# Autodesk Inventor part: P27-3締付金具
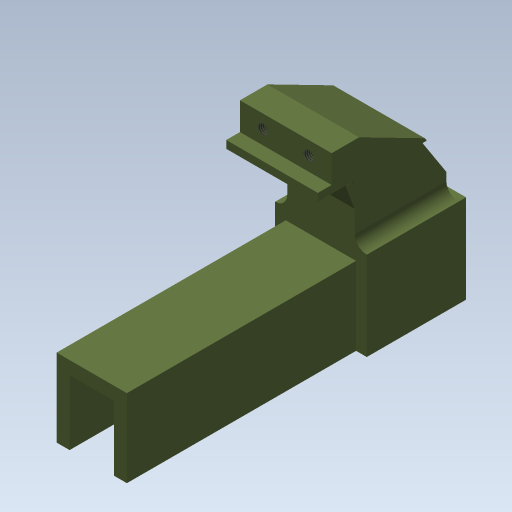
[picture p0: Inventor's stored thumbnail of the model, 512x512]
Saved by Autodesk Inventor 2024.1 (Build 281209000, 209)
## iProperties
Created: 2008-07
Part Number: P27-3締付金具
Document SubType Name: Modeling
Designer: y-shimohigashi
Density: 1 g/cm^3
Stock Number: P24-3締付金具
Material: 一般
Appearance: Olive Drab
Author: y-shimohigashi
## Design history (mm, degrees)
sketch "スケッチ3"
  geometry: L1 (43, 22)-(43, 80); L2 (43, 80)-(38, 80); L3 (38, 80)-(38, 93); L4 (38, 93)-(16, 127); L5 (16, 127)-(-27, 149); L6 (-27, 149)-(-45, 149); L7 (-45, 149)-(-45, 131); L8 (-45, 131)-(-54, 131); L9 (-54, 131)-(-54, 126); L10 (-54, 126)-(-44, 126); L11 (-44, 126)-(-31, 126); L12 (-31, 126)-(-22, 102); L13 (-22, 102)-(-22, 22); L14 (-22, 22)-(43, 22); 1 further point
  constraints: 28 end point, 6 parallel, 1 horizontal, 1 perpendicular, 1 vertical
  dimensions: "d4" = 58 distance of L1.start L1.end; "d5" = 13 distance of L2.end L3.end; "d6" = 34 vertical distance of L3.end L4.end; "d7" = 22 vertical distance of L4.end L5.end; "d8" = 5 distance of L1.end L2.end; "d9" = 22 horizontal distance of L3.end L4.end; "d10" = 43 horizontal distance of L4.end L5.end; "d11" = 18 distance of L5.end L6.end; "d12" = 9 distance of L7.end L8.end; "d13" = 18 distance of L6.end L7.end; "d14" = 5 distance of L8.end L9.end; "d15" = 10 distance of L9.end L10.end; "d16" = 24 vertical distance of L11.end L12.end; "d17" = 80 distance of L12.end L13.end; "d18" = 65 distance between parallel lines of L1 L13; "d19" = 13 distance of L10.end L11.end; "d66" = 43 distance from line of L1 point (0, 0); "d67" = 22 distance from line of point (0, 0) L14
extrude "押し出し2" new body sketch "スケッチ3" stored distance "d20" = 60; taper "d21" = 0 deg
sketch "スケッチ4"
  geometry: L1 (0, 0)-(60, 0) reference; L2 (60, 0)-(52, 0); L3 (52, 0)-(52, -45); L4 (52, -45)-(60, -45); L5 (60, -45)-(60, 0); L6 (0, 0)-(8, 0); L7 (8, 0)-(8, -45); L8 (8, -45)-(0, -45); L9 (0, -45)-(0, 0)
  constraints: 16 end point, 4 parallel, 2 collinear, 2 horizontal, 2 perpendicular
  dimensions: "d22" = 8 distance of L3.end L4.end; "d23" = 45 distance of L4.end L1.end
extrude "押し出し3" cut sketch "スケッチ4" extent not by distance; stored distance "d24" = 60; taper "d25" = 0 deg
sketch "スケッチ9"
  geometry: L1 (-60, 58)-(-60, 0) reference; L2 (-60, 0)-(0, 0) reference; L3 (0, 0)-(0, 58) reference; L4 (0, 58)-(-60, 58) reference; L5 (-53, 51)-(-53, 0); L6 (-7, 0)-(-7, 51); L7 (-7, 51)-(-53, 51); L8 (-53, 0)-(-44.5, 0); L9 (-44.5, 42.5)-(-15.5, 42.5); L10 (-15.5, 42.5)-(-15.5, 0); L11 (-44.5, 42.5)-(-44.5, 0); L12 (-15.5, 0)-(-7, 0)
  constraints: 16 end point, 4 point on line, 2 parallel, 2 perpendicular, 1 collinear
  dimensions: "d68" = 7 distance between parallel lines of L7 L4; "d69" = 7 distance between parallel lines of L5 L1 (= d68); "d70" = 7 distance between parallel lines of L3 L6 (= d68); "d71" = 8.5 distance between parallel lines of L9 L7; "d72" = 8.5 distance between parallel lines of L11 L5 (= d71)
extrude "押し出し6" join sketch "スケッチ9" distance "d74" = 215; taper "d75" = 0 deg
sketch "スケッチ10"
  geometry: L1 (60, 0)-(0, 0) reference; 2 further points
  constraints: 1 midpoint, 1 vertical alignment
  dimensions: "d85" = 25.5 distance from line of L1 point (30, -25.5)
hole "穴4" sketch "スケッチ10" diameter "d76" = 16; stored, may be unused: countersink angle "d80" = 90 deg, drill point angle "d82" = 118 deg; dims "d77" = 6, "d78" = 36, "d79" = 15, "d81" = 8
feature "ねじ1" dims "d83" = 10, "d84" = 0
sketch "スケッチ11"
  geometry: L1 (30, -152.4)-(30, 25.4) reference; L2 (60, -18)-(60, 0) reference; 3 further points
  constraints: 2 horizontal alignment, 1 midpoint, 1 symmetric about line
  dimensions: "d88" = 30 distance of point (45, -9) point (15, -9)
hole "穴5" sketch "スケッチ11" diameter "d89" = 6.647; stored, may be unused: countersink angle "d93" = 90 deg, drill point angle "d95" = 118 deg; dims "d90" = 6, "d91" = 36, "d92" = 15, "d94" = 8
fillet "フィレット4" dims "d96" = 8
node "ソリッド1"
node "ソリッド ボディ"
node "サーフェス ボディ"
node "投影ループ2"
